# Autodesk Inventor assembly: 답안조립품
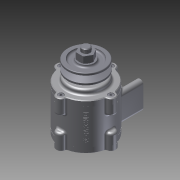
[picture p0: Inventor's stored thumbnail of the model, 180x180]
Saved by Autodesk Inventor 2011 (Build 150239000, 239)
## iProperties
Created: 2015-03
Part Number: 답안조립품
Document SubType Name: Assembly
Designer: LINEART07
Author: LINEART07
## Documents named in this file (11)
- C:\Users\LINEART07\Desktop\박주환\답안조립품.iam
- C:\Users\LINEART07\Desktop\박주환\본체.ipt
- C:\Users\LINEART07\Desktop\박주환\축.ipt
- C:\Users\LINEART07\Desktop\박주환\커버2.ipt
- C:\Users\LINEART07\Desktop\박주환\베어링 6204.ipt
- C:\Users\LINEART07\Desktop\박주환\커버.ipt
- C:\Users\LINEART07\Desktop\박주환\오일실.ipt
- C:\Users\LINEART07\Desktop\박주환\키(4 x 4 x 12).ipt
- C:\Users\LINEART07\Desktop\박주환\V벨트풀리.ipt
- C:\Users\LINEART07\Desktop\박주환\너트 M12x1.25.ipt
- C:\Users\LINEART07\Desktop\박주환\M 4 x 12.ipt
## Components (14 placed, 6 different names)
1. KS B 2023 6204 - 20 x 47 x 14:1
2. KS B 2023 6204 - 20 x 47 x 14:2
3. KS B 2804 D D - 20 32 8:1
4. KS B 1311 (I) 4 x 4 x 12:1 — 각도:2, 각도:3
5. 그루브 풀리1:1 — 각도:3
6. KS B 1012 클래스 1 일반 - 미터 M12x1.25:1 — 각도:4
7. KS B 1003 - 미터 M 4 x 12:2
8. KS B 1003 - 미터 M 4 x 12:3
9. KS B 1003 - 미터 M 4 x 12:4
10. KS B 1003 - 미터 M 4 x 12:5
11. KS B 1003 - 미터 M 4 x 12:1
12. KS B 1003 - 미터 M 4 x 12:6
13. KS B 1003 - 미터 M 4 x 12:7
14. KS B 1003 - 미터 M 4 x 12:8
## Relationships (3: Angle 3)
- 각도:2 [Angle]: KS B 1311 (I) 4 x 4 x 12:1
- 각도:3 [Angle]: KS B 1311 (I) 4 x 4 x 12:1 ↔ 그루브 풀리1:1
- 각도:4 [Angle]: KS B 1012 클래스 1 일반 - 미터 M12x1.25:1
